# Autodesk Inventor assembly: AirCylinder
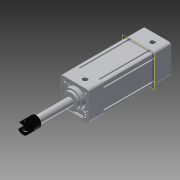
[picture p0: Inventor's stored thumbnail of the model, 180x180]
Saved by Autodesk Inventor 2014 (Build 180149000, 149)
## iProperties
Shininess: 64.0
Length Units: 11269
Angle Units: 11279
Time Units: 11290
Mass Units: 11283
Length Display Precision: 3
Angle Display Precision: 2
Compacted: True
Created: 2002-12
Part Number: AirCylinder
Document SubType Name: Assembly
Designer: dayb
Mass: 151.546 g
Surface Area: 600.419 cm^2
Volume: 151.546 cm^3
Density: 1 g/cm^3
Density: 0.0
Volumn: 0.0
Area: 0.0
PropertySet Name: Model Information
Control State: 0
Master: False
Checked Out: False
Author: dayb
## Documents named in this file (6)
- C:\Users\iTools\Desktop\tutorial files\Tube and Pipe\Air System\AirCylinder.iam
- C:\Users\iTools\Desktop\tutorial files\Tube and Pipe\Air System\PistonCover.ipt
- C:\Users\iTools\Desktop\tutorial files\Tube and Pipe\Air System\pushrod.ipt
- C:\Users\iTools\Desktop\tutorial files\Tube and Pipe\Air System\rodend.ipt
- C:\Users\iTools\Desktop\tutorial files\Tube and Pipe\Air System\EndCover.ipt
- C:\Users\iTools\Desktop\tutorial files\Tube and Pipe\Air System\AirCylinderBody.ipt
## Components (5 placed, 5 different names)
1. PistonCover:1 — Flush:1, Flush:2, Mate:1, Flush:4
2. AirCylinderBody:1 — Flush:2, Flush:3, Mate:1
3. EndCover:1 — Flush:3
4. pushrod:1 — Flush:4, Flush:5
5. rodend:1 — Flush:5
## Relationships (6: Flush 5, Mate 1)
- Flush:1: PistonCover:1
- Flush:2: PistonCover:1 ↔ AirCylinderBody:1
- Flush:3: AirCylinderBody:1 ↔ EndCover:1
- Mate:1: PistonCover:1 ↔ AirCylinderBody:1
- Flush:4: PistonCover:1 ↔ pushrod:1
- Flush:5: pushrod:1 ↔ rodend:1
